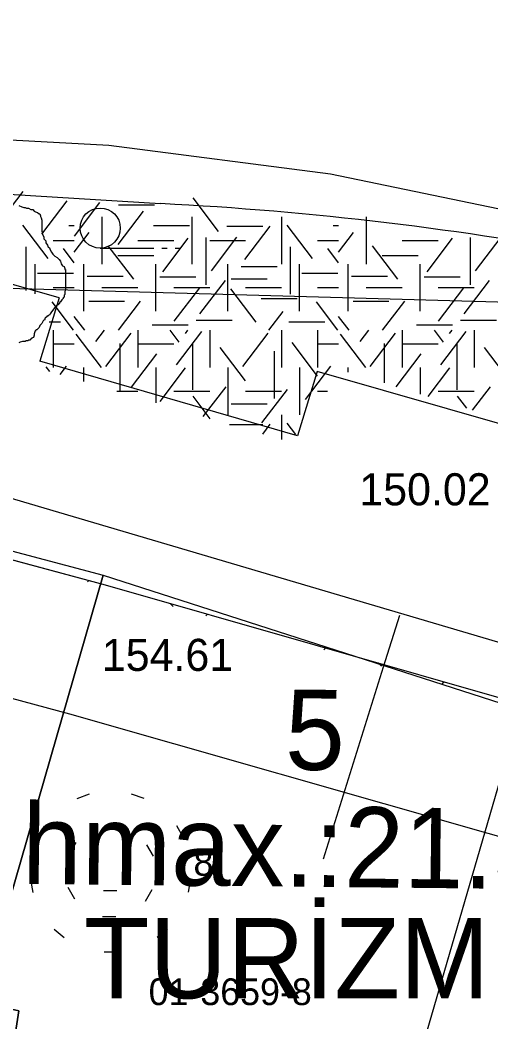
# Model space of a CAD drawing. Extents: x 419677 to 421689, y 4450851 to 4452923.
# Drawn here: x 420249.96 to 420267.57, y 4451941.04 to 4451978.52 of the extents above; entities that cross this region are included whole.
import ezdxf

# ---------------------------------------------------------------- set-up
doc = ezdxf.new("R2010")
doc.units = 0
for name, color, linetype in [('AA_HH', 7, 'Continuous'), ('Level 10', 7, 'Continuous'), ('Level 15', 7, 'Continuous'), ('Level 19', 7, 'Continuous'), ('Level 20', 7, 'Continuous'), ('Level 27', 7, 'Continuous'), ('Level 3', 7, 'Continuous'), ('Level 34', 7, 'Continuous'), ('Level 38', 7, 'Continuous'), ('Level 41', 7, 'Continuous'), ('Level 62', 7, 'Continuous'), ('Level 9', 7, 'Continuous'), ('MULKIYET SINIRI', 7, 'Continuous'), ('PARSEL KODU', 7, 'Continuous'), ('PARSEL NUMARASI', 7, 'Continuous')]:
    doc.layers.add(name, color=color, linetype=linetype)

msp = doc.modelspace()

# ---------------------------------------------------------------- linework, layer by layer
at = {"layer": 'AA_HH'}
for p, q in [((420252.959, 4451969.987), (420254.959, 4451969.987)), ((420255.259, 4451969.987), (420255.459, 4451969.987)), ((420255.759, 4451969.987), (420255.959, 4451969.987))]:
    msp.add_line(p, q, dxfattribs=at)
msp.add_lwpolyline([(420390.75, 4451923.523), (420355.577, 4451937.004), (420307.443, 4451957.787), (420280.515, 4451967.9), (420273.647, 4451970.301), (420269.934, 4451971.02), (420261.568, 4451972.752), (420253.278, 4451973.826), (420241.307, 4451974.471), (420234.881, 4451973.555), (420234.717, 4451973.483)], dxfattribs=at)
for points in [[(420253.07, 4451957.757), (420248.46, 4451941.78), (420249.914, 4451941.452), (420248.847, 4451934.599), (420231.114, 4451939.515), (420234.427, 4451962.705)], [(420253.07, 4451957.757), (420268.667, 4451952.723), (420262.187, 4451930.463), (420248.847, 4451934.599), (420249.914, 4451941.452), (420248.46, 4451941.78)], [(420259.458, 4451921.085), (420263.996, 4451919.943), (420268.928, 4451918.585), (420273.471, 4451917.713), (420278.603, 4451916.183), (420282.028, 4451915.2), (420284.321, 4451935.777), (420285.52, 4451935.517), (420286.365, 4451941.471), (420286.21, 4451948.504), (420268.667, 4451952.723), (420259.458, 4451921.085)]]:
    msp.add_lwpolyline(points, close=True, dxfattribs=at)
msp.add_circle((420252.959, 4451970.737), 0.75, dxfattribs=at)
at = {"layer": 'Level 10'}
msp.add_lwpolyline([(420320.676, 4451952.286), (420287.846, 4451965.918), (420283.914, 4451959.364), (420283.477, 4451950.626), (420231.702, 4451965.918)], dxfattribs=at)
at = {"layer": 'Level 15'}
msp.add_lwpolyline([(420414.132, 4451911.018), (420415.765, 4451915.419), (420282.101, 4451967.569), (420224.504, 4451969.178), (420220.055, 4451958.563), (420205.131, 4451843.779), (420215.712, 4451841.911), (420221.376, 4451877.395), (420222.223, 4451877.252)], dxfattribs=at)
at = {"layer": 'Level 20'}
for p, q in [((420263.551, 4451954.326), (420264.156, 4451956.263)), ((420263.551, 4451954.326), (420264.156, 4451956.263)), ((420261.309, 4451947.144), (420263.551, 4451954.326)), ((420261.309, 4451947.144), (420263.551, 4451954.326))]:
    msp.add_line(p, q, dxfattribs=at)
msp.add_lwpolyline([(420236.733, 4451942.109), (420238.791, 4451956.081), (420251.808, 4451952.573), (420267.449, 4451948.101), (420281.49, 4451944.095)], dxfattribs=at)
msp.add_lwpolyline([(420236.733, 4451942.109), (420238.791, 4451956.081), (420251.808, 4451952.573), (420267.449, 4451948.101), (420281.49, 4451944.095)], dxfattribs=at)
at = {"layer": 'Level 27'}
msp.add_lwpolyline([(420248.61, 4451958.613), (420253.146, 4451957.391), (420268.822, 4451952.909), (420285.985, 4451948.012), (420287.724, 4451962.476), (420333.69, 4451943.911), (420338.452, 4451942.062), (420340.782, 4451941.146)], dxfattribs=at)
msp.add_lwpolyline([(420248.61, 4451958.613), (420253.146, 4451957.391), (420268.822, 4451952.909), (420285.985, 4451948.012), (420287.724, 4451962.476), (420333.69, 4451943.911), (420338.452, 4451942.062), (420340.782, 4451941.146)], dxfattribs=at)
msp.add_lwpolyline([(420248.61, 4451958.613), (420253.146, 4451957.391), (420268.822, 4451952.909), (420285.985, 4451948.012), (420287.724, 4451962.476), (420333.69, 4451943.911), (420338.452, 4451942.062), (420340.782, 4451941.146)], dxfattribs=at)
at = {"layer": 'Level 3'}
for points in [[(420249.921, 4451971.582), (420250.025, 4451971.53), (420250.102, 4451971.504), (420250.154, 4451971.504), (420250.206, 4451971.478), (420250.258, 4451971.478), (420250.284, 4451971.478), (420250.362, 4451971.427), (420250.44, 4451971.427), (420250.492, 4451971.375), (420250.543, 4451971.349), (420250.621, 4451971.323), (420250.673, 4451971.271), (420250.699, 4451971.271), (420250.725, 4451971.193), (420250.725, 4451971.167), (420250.751, 4451971.115), (420250.777, 4451971.037), (420250.777, 4451971.011), (420250.777, 4451970.933), (420250.777, 4451970.881), (420250.777, 4451970.803), (420250.777, 4451970.777), (420250.777, 4451970.699), (420250.777, 4451970.622), (420250.803, 4451970.492), (420250.855, 4451970.414), (420250.855, 4451970.336), (420250.933, 4451970.258), (420250.933, 4451970.18), (420250.984, 4451970.102), (420251.01, 4451970.024), (420251.062, 4451969.998), (420251.088, 4451969.92), (420251.14, 4451969.842), (420251.192, 4451969.765), (420251.27, 4451969.687), (420251.348, 4451969.635), (420251.399, 4451969.583), (420251.425, 4451969.557), (420251.477, 4451969.505), (420251.503, 4451969.401), (420251.555, 4451969.323), (420251.607, 4451969.297), (420251.633, 4451969.219), (420251.633, 4451969.193), (420251.659, 4451969.193), (420251.659, 4451969.167), (420251.659, 4451969.141), (420251.659, 4451969.089), (420251.659, 4451968.986), (420251.659, 4451968.934), (420251.659, 4451968.856), (420251.659, 4451968.778), (420251.659, 4451968.7), (420251.659, 4451968.622), (420251.659, 4451968.544), (420251.659, 4451968.492), (420251.659, 4451968.414), (420251.633, 4451968.362), (420251.633, 4451968.258), (420251.607, 4451968.232), (420251.607, 4451968.155), (420251.581, 4451968.129), (420251.581, 4451968.103), (420251.529, 4451968.051), (420251.477, 4451967.973), (420251.451, 4451967.973), (420251.451, 4451967.947), (420251.425, 4451967.921), (420251.399, 4451967.895), (420251.399, 4451967.869), (420251.374, 4451967.869), (420251.348, 4451967.869)], [(420251.348, 4451967.869), (420251.296, 4451967.817), (420251.14, 4451967.609), (420251.088, 4451967.531), (420251.062, 4451967.479), (420251.036, 4451967.479), (420251.01, 4451967.453), (420250.984, 4451967.453), (420250.984, 4451967.427), (420250.958, 4451967.427), (420250.958, 4451967.401), (420250.933, 4451967.401), (420250.933, 4451967.375), (420250.907, 4451967.375), (420250.881, 4451967.298), (420250.855, 4451967.298), (420250.829, 4451967.272), (420250.777, 4451967.168), (420250.699, 4451967.09), (420250.673, 4451967.012), (420250.595, 4451966.934), (420250.569, 4451966.934), (420250.543, 4451966.908), (420250.543, 4451966.882), (420250.517, 4451966.882), (420250.517, 4451966.856), (420250.492, 4451966.778), (420250.492, 4451966.726), (420250.466, 4451966.648), (420250.388, 4451966.622), (420250.388, 4451966.596), (420250.362, 4451966.596), (420250.362, 4451966.57), (420250.336, 4451966.57), (420250.336, 4451966.544), (420250.31, 4451966.544), (420250.284, 4451966.544), (420250.258, 4451966.519), (420250.232, 4451966.519), (420250.206, 4451966.519), (420250.18, 4451966.519), (420250.154, 4451966.493), (420250.128, 4451966.493), (420250.102, 4451966.493), (420250.076, 4451966.493), (420250.051, 4451966.493), (420249.973, 4451966.467), (420249.921, 4451966.441)]]:
    msp.add_lwpolyline(points, dxfattribs=at)
at = {"layer": 'Level 34'}
for p, q in [((420252.482, 4451957.502), (420252.536, 4451957.555)), ((420252.482, 4451957.502), (420252.536, 4451957.555)), ((420255.683, 4451956.584), (420255.572, 4451956.697)), ((420255.683, 4451956.584), (420255.572, 4451956.697)), ((420255.683, 4451956.584), (420255.683, 4451956.584)), ((420255.683, 4451956.584), (420255.683, 4451956.584)), ((420256.902, 4451956.234), (420256.968, 4451956.298)), ((420256.902, 4451956.234), (420256.968, 4451956.298)), ((420261.324, 4451954.965), (420261.393, 4451955.033)), ((420261.324, 4451954.965), (420261.393, 4451955.033)), ((420263.473, 4451954.348), (420263.351, 4451954.473)), ((420263.473, 4451954.348), (420263.351, 4451954.473)), ((420265.744, 4451953.697), (420265.817, 4451953.768)), ((420265.744, 4451953.697), (420265.817, 4451953.768)), ((420265.744, 4451953.697), (420265.744, 4451953.697)), ((420265.744, 4451953.697), (420265.744, 4451953.697))]:
    msp.add_line(p, q, dxfattribs=at)
at = {"layer": 'Level 38'}
for p, q in [((420252.548, 4451949.562), (420252.082, 4451949.392)), ((420252.548, 4451949.562), (420252.082, 4451949.392)), ((420254.601, 4451949.397), (420254.134, 4451949.566)), ((420254.601, 4451949.397), (420254.134, 4451949.566)), ((420250.87, 4451948.369), (420250.622, 4451947.939)), ((420250.87, 4451948.369), (420250.622, 4451947.939)), ((420253.645, 4451948.336), (420253.149, 4451948.336)), ((420253.645, 4451948.336), (420253.149, 4451948.336)), ((420256.067, 4451947.951), (420255.819, 4451948.381)), ((420256.067, 4451947.951), (420255.819, 4451948.381)), ((420252.045, 4451947.755), (420251.797, 4451947.326)), ((420252.045, 4451947.755), (420251.797, 4451947.326)), ((420254.948, 4451947.241), (420254.7, 4451947.67)), ((420254.948, 4451947.241), (420254.7, 4451947.67)), ((420252.868, 4451947.239), (420252.62, 4451946.81)), ((420252.868, 4451947.239), (420252.62, 4451946.81)), ((420254.09, 4451946.786), (420253.842, 4451947.215)), ((420254.09, 4451946.786), (420253.842, 4451947.215)), ((420250.352, 4451946.376), (420250.438, 4451945.888)), ((420250.352, 4451946.376), (420250.438, 4451945.888)), ((420251.748, 4451946.079), (420251.996, 4451945.65)), ((420251.748, 4451946.079), (420251.996, 4451945.65)), ((420256.261, 4451945.902), (420256.347, 4451946.39)), ((420256.261, 4451945.902), (420256.347, 4451946.39)), ((420253.086, 4451945.955), (420253.582, 4451945.955)), ((420253.086, 4451945.955), (420253.582, 4451945.955)), ((420254.651, 4451945.565), (420254.899, 4451945.994)), ((420254.651, 4451945.565), (420254.899, 4451945.994)), ((420253.051, 4451944.984), (420253.547, 4451944.984)), ((420253.051, 4451944.984), (420253.547, 4451944.984)), ((420251.235, 4451944.517), (420251.615, 4451944.198)), ((420251.235, 4451944.517), (420251.615, 4451944.198)), ((420255.092, 4451944.207), (420255.472, 4451944.526)), ((420255.092, 4451944.207), (420255.472, 4451944.526)), ((420253.107, 4451943.66), (420253.603, 4451943.66)), ((420253.107, 4451943.66), (420253.603, 4451943.66))]:
    msp.add_line(p, q, dxfattribs=at)
at = {"layer": 'Level 41'}
for p, q in [((420249.127, 4451970.859), (420250.076, 4451972.109)), ((420250.778, 4451970.508), (420251.728, 4451971.757)), ((420252.001, 4451970.439), (420252.95, 4451971.688)), ((420253.648, 4451971.609), (420254.991, 4451971.609)), ((420257.381, 4451970.614), (420256.431, 4451971.863)), ((420253.024, 4451971.16), (420253.024, 4451969.393)), ((420253.626, 4451970.122), (420254.575, 4451971.372)), ((420256.382, 4451971.16), (420256.382, 4451969.393)), ((420259.739, 4451971.16), (420259.739, 4451969.393)), ((420262.903, 4451971.16), (420262.903, 4451969.393)), ((420251.017, 4451969.596), (420250.068, 4451970.845)), ((420251.787, 4451970.836), (420251.991, 4451970.836)), ((420254.954, 4451970.836), (420256.297, 4451970.836)), ((420257.696, 4451970.803), (420259.039, 4451970.803)), ((420258.366, 4451969.562), (420259.316, 4451970.812)), ((420260.896, 4451969.596), (420259.947, 4451970.845)), ((420261.666, 4451970.836), (420261.87, 4451970.836)), ((420251.991, 4451969.83), (420252.55, 4451970.566)), ((420256.914, 4451970.388), (420256.914, 4451968.62)), ((420257.114, 4451969.142), (420258.063, 4451970.391)), ((420261.87, 4451969.83), (420262.429, 4451970.566)), ((420266.793, 4451970.388), (420266.793, 4451968.62)), ((420266.993, 4451969.142), (420267.942, 4451970.391)), ((420250.178, 4451970.038), (420250.178, 4451968.396)), ((420251.203, 4451970.276), (420251.991, 4451970.276)), ((420254.211, 4451968.825), (420253.262, 4451970.075)), ((420254.367, 4451970.276), (420255.71, 4451970.276)), ((420255.303, 4451969.106), (420256.253, 4451970.356)), ((420257.053, 4451970.276), (420258.396, 4451970.276)), ((420260.057, 4451970.038), (420260.057, 4451968.27)), ((420261.082, 4451970.276), (420261.87, 4451970.276)), ((420264.09, 4451968.825), (420263.141, 4451970.075)), ((420264.246, 4451970.276), (420265.589, 4451970.276)), ((420265.182, 4451969.106), (420266.132, 4451970.356)), ((420251.991, 4451969.436), (420251.585, 4451969.97)), ((420253.621, 4451969.716), (420254.964, 4451969.716)), ((420261.87, 4451969.436), (420261.464, 4451969.97)), ((420263.5, 4451969.716), (420264.843, 4451969.716)), ((420250.532, 4451968.283), (420250.532, 4451969.393)), ((420252.353, 4451967.625), (420252.353, 4451969.393)), ((420255.039, 4451967.625), (420255.039, 4451969.393)), ((420257.725, 4451967.625), (420257.725, 4451969.393)), ((420258.23, 4451969.295), (420259.573, 4451969.295)), ((420260.411, 4451967.625), (420260.411, 4451969.393)), ((420262.232, 4451967.625), (420262.232, 4451969.393)), ((420264.918, 4451967.625), (420264.918, 4451969.393)), ((420250.614, 4451969.05), (420251.957, 4451969.05)), ((420252.476, 4451968.944), (420253.819, 4451968.944)), ((420255.193, 4451968.91), (420256.536, 4451968.91)), ((420260.493, 4451969.05), (420261.836, 4451969.05)), ((420262.355, 4451968.944), (420263.698, 4451968.944)), ((420265.072, 4451968.91), (420266.415, 4451968.91)), ((420251.203, 4451968.509), (420251.991, 4451968.509)), ((420253.024, 4451968.509), (420254.367, 4451968.509)), ((420255.71, 4451968.509), (420257.053, 4451968.509)), ((420256.689, 4451967.528), (420257.638, 4451968.778)), ((420257.856, 4451968.839), (420259.199, 4451968.839)), ((420258.396, 4451968.509), (420259.739, 4451968.509)), ((420261.082, 4451968.509), (420261.87, 4451968.509)), ((420262.903, 4451968.509), (420264.246, 4451968.509)), ((420265.589, 4451968.509), (420266.932, 4451968.509)), ((420266.568, 4451967.528), (420267.517, 4451968.778)), ((420255.729, 4451967.249), (420256.678, 4451968.498)), ((420258.792, 4451967.214), (420257.842, 4451968.463)), ((420265.608, 4451967.249), (420266.557, 4451968.498)), ((420251.962, 4451966.916), (420251.16, 4451967.972)), ((420252.53, 4451967.998), (420253.872, 4451967.998)), ((420253.638, 4451966.916), (420254.467, 4451968.007)), ((420258.975, 4451968.102), (420260.318, 4451968.102)), ((420261.841, 4451966.916), (420261.039, 4451967.972)), ((420262.409, 4451967.998), (420263.751, 4451967.998)), ((420263.517, 4451966.916), (420264.346, 4451968.007)), ((420252.385, 4451966.916), (420251.991, 4451967.434)), ((420259.258, 4451966.916), (420259.795, 4451967.622)), ((420262.264, 4451966.916), (420261.87, 4451967.434)), ((420251.05, 4451967.228), (420251.478, 4451967.228)), ((420254.9, 4451967.122), (420256.243, 4451967.122)), ((420256.552, 4451967.297), (420257.895, 4451967.297)), ((420260.014, 4451967.228), (420261.357, 4451967.228)), ((420264.779, 4451967.122), (420266.122, 4451967.122)), ((420266.431, 4451967.297), (420267.774, 4451967.297)), ((420251.203, 4451966.916), (420251.203, 4451965.518)), ((420251.203, 4451966.916), (420251.203, 4451965.518)), ((420253.012, 4451965.518), (420252.063, 4451966.768)), ((420252.801, 4451966.499), (420253.118, 4451966.916)), ((420253.172, 4451965.553), (420254.121, 4451966.803)), ((420254.367, 4451966.916), (420254.367, 4451965.518)), ((420255.916, 4451966.464), (420255.572, 4451966.916)), ((420255.809, 4451965.622), (420256.759, 4451966.872)), ((420256.142, 4451966.796), (420256.233, 4451966.916)), ((420257.053, 4451966.916), (420257.053, 4451965.518)), ((420258.286, 4451965.553), (420259.235, 4451966.803)), ((420259.739, 4451966.916), (420259.739, 4451965.518)), ((420261.082, 4451966.916), (420261.082, 4451965.518)), ((420261.082, 4451966.916), (420261.082, 4451965.518)), ((420262.891, 4451965.518), (420261.942, 4451966.768)), ((420262.68, 4451966.499), (420262.997, 4451966.916)), ((420263.051, 4451965.553), (420264, 4451966.803)), ((420264.246, 4451966.916), (420264.246, 4451965.518)), ((420265.795, 4451966.464), (420265.451, 4451966.916)), ((420265.688, 4451965.622), (420266.638, 4451966.872)), ((420266.021, 4451966.796), (420266.112, 4451966.916)), ((420266.932, 4451966.916), (420266.932, 4451965.518)), ((420251.203, 4451966.402), (420251.991, 4451966.402)), ((420253.692, 4451966.414), (420253.692, 4451964.647)), ((420254.367, 4451966.402), (420255.71, 4451966.402)), ((420256.409, 4451966.449), (420256.409, 4451964.682)), ((420258.393, 4451965.027), (420257.444, 4451966.276)), ((420261.083, 4451965.202), (420260.134, 4451966.451)), ((420261.082, 4451966.402), (420261.87, 4451966.402)), ((420263.571, 4451966.414), (420263.571, 4451964.942)), ((420264.246, 4451966.402), (420265.589, 4451966.402)), ((420266.288, 4451966.449), (420266.288, 4451964.682)), ((420268.272, 4451965.027), (420267.323, 4451966.276)), ((420254.132, 4451964.781), (420255.081, 4451966.031)), ((420259.457, 4451966.128), (420259.457, 4451964.361)), ((420264.027, 4451964.802), (420264.96, 4451966.031)), ((420251.076, 4451965.371), (420250.938, 4451965.552)), ((420251.46, 4451965.258), (420251.701, 4451965.575)), ((420252.353, 4451964.995), (420252.353, 4451965.518)), ((420255.039, 4451965.518), (420255.039, 4451964.205)), ((420255.198, 4451964.256), (420256.147, 4451965.506)), ((420257.725, 4451965.518), (420257.725, 4451963.751)), ((420260.411, 4451965.518), (420260.411, 4451963.751)), ((420260.411, 4451965.518), (420260.411, 4451963.751)), ((420260.631, 4451964.325), (420261.58, 4451965.575)), ((420262.232, 4451965.352), (420262.232, 4451965.518)), ((420264.918, 4451965.518), (420264.918, 4451964.529)), ((420265.215, 4451964.438), (420266.026, 4451965.506)), ((420256.813, 4451963.684), (420257.666, 4451964.804)), ((420266.879, 4451963.929), (420267.545, 4451964.804)), ((420253.581, 4451964.634), (420254.367, 4451964.634)), ((420255.71, 4451964.634), (420257.053, 4451964.634)), ((420257.076, 4451963.606), (420256.431, 4451964.454)), ((420258.396, 4451964.634), (420259.739, 4451964.634)), ((420259.006, 4451963.45), (420259.955, 4451964.7)), ((420261.082, 4451964.634), (420261.456, 4451964.634)), ((420265.589, 4451964.634), (420266.932, 4451964.634)), ((420266.658, 4451963.997), (420266.31, 4451964.454)), ((420257.856, 4451964.164), (420259.199, 4451964.164)), ((420259.739, 4451963.751), (420259.739, 4451962.823)), ((420257.798, 4451963.394), (420259.039, 4451963.394)), ((420259.033, 4451963.031), (420259.316, 4451963.403)), ((420260.268, 4451963.014), (420259.947, 4451963.436))]:
    msp.add_line(p, q, dxfattribs=at)
at = {"layer": 'Level 62'}
for p, q in [((420251.432, 4451968.131), (420241.885, 4451970.865)), ((420251.432, 4451968.131), (420250.706, 4451965.756)), ((420260.336, 4451962.962), (420250.706, 4451965.756)), ((420261.072, 4451965.371), (420260.336, 4451962.962)), ((420270.658, 4451962.626), (420261.072, 4451965.371))]:
    msp.add_line(p, q, dxfattribs=at)
msp.add_lwpolyline([(420255.213, 4451971.65), (420247.303, 4451972.13)], dxfattribs=at)
msp.add_ellipse((420249.054, 4451888.13), major_axis=(101.534, 0), ratio=0.824102, start_param=1.175682, end_param=1.510101, dxfattribs=at)
msp.add_open_spline([(420301.269, 4451982.918), (420289.191, 4451973.63), (420250.246, 4451985.779), (420242.55, 4451988.153), (420241.405, 4451988.503)], degree=3, dxfattribs=at)
at = {"layer": 'Level 9'}
msp.add_lwpolyline([(420425.574, 4451910.283), (420391.286, 4451924.082), (420343.881, 4451942.651), (420287.846, 4451965.918), (420283.914, 4451959.364), (420283.477, 4451950.626), (420231.702, 4451965.918), (420228.644, 4451941.45), (420224.602, 4451910.32), (420222.636, 4451894.154), (420216.956, 4451865.1), (420209.201, 4451819.114), (420204.832, 4451797.924), (420203.303, 4451783.287), (420202.429, 4451776.297), (420195.86, 4451755.756)], dxfattribs=at)
msp.add_lwpolyline([(420425.574, 4451910.283), (420391.286, 4451924.082), (420343.881, 4451942.651), (420287.846, 4451965.918), (420283.914, 4451959.364), (420283.477, 4451950.626), (420231.702, 4451965.918), (420228.644, 4451941.45), (420224.602, 4451910.32), (420222.636, 4451894.154), (420216.956, 4451865.1), (420209.201, 4451819.114), (420204.832, 4451797.924), (420203.303, 4451783.287), (420202.429, 4451776.297), (420195.86, 4451755.756)], dxfattribs=at)
at = {"layer": 'MULKIYET SINIRI'}
msp.add_lwpolyline([(420231.299, 4451939.533), (420231.802, 4451942.949), (420234.664, 4451962.372), (420253.146, 4451957.391), (420268.822, 4451952.909), (420285.985, 4451948.012), (420285.171, 4451941.809), (420284.013, 4451934.694), (420283.847, 4451933.672), (420282.403, 4451924.555), (420262.057, 4451930.52), (420261.333, 4451930.733), (420261.084, 4451930.806), (420248.63, 4451934.454)], close=True, dxfattribs=at)
msp.add_lwpolyline([(420231.299, 4451939.533), (420231.802, 4451942.949), (420234.664, 4451962.372), (420253.146, 4451957.391), (420268.822, 4451952.909), (420285.985, 4451948.012), (420285.171, 4451941.809), (420284.013, 4451934.694), (420283.847, 4451933.672), (420282.403, 4451924.555), (420262.057, 4451930.52), (420261.333, 4451930.733), (420261.084, 4451930.806), (420248.63, 4451934.454)], close=True, dxfattribs=at)

# ---------------------------------------------------------------- texts
at = {"layer": 'AA_HH'}
msp.add_text('150.02 ', height=1.2, rotation=359.9981, dxfattribs=at).set_placement((420262.646, 4451960.366))
msp.add_text('154.61 ', height=1.2, dxfattribs=at).set_placement((420253.021, 4451954.172))
at = {"layer": 'Level 19'}
msp.add_text('TURİZM', height=3, rotation=359.9948, dxfattribs=at).set_placement((420252.353, 4451941.925))
msp.add_text('TURİZM', height=3, rotation=359.9948, dxfattribs=at).set_placement((420252.353, 4451941.925))
at = {"layer": 'Level 20'}
msp.add_text('5', height=3, rotation=359.4141, dxfattribs=at).set_placement((420259.86, 4451950.48))
msp.add_text('5', height=3, rotation=359.4141, dxfattribs=at).set_placement((420259.86, 4451950.48))
at = {"layer": 'Level 27'}
msp.add_text('hmax.:21.50', height=2.99999, rotation=359.4141, dxfattribs=at).set_placement((420250.028, 4451946.208))
msp.add_text('hmax.:21.50', height=2.99999, rotation=359.4141, dxfattribs=at).set_placement((420250.028, 4451946.208))
at = {"layer": 'PARSEL KODU'}
msp.add_text('01-3659-8', height=1, dxfattribs=at).set_placement((420254.771, 4451941.672))
msp.add_text('01-3659-8', height=1, dxfattribs=at).set_placement((420254.771, 4451941.672))
at = {"layer": 'PARSEL NUMARASI'}
msp.add_text('8', height=1, dxfattribs=at).set_placement((420256.446, 4451946.508))
msp.add_text('8', height=1, dxfattribs=at).set_placement((420256.446, 4451946.508))

doc.saveas('drawing.dxf')
